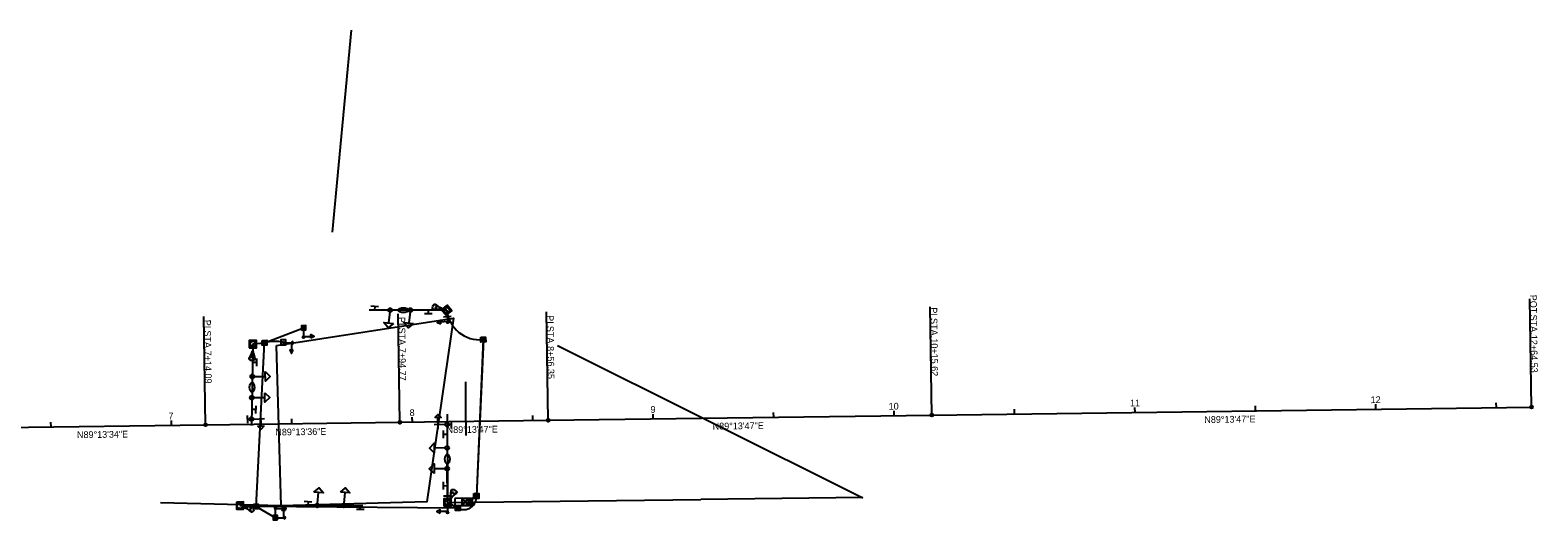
# Model space of a CAD drawing. Extents: x 1369241 to 1370511, y 405823 to 406278.
# Drawn here: x 1369885 to 1370511, y 405870 to 406073 of the extents above; entities that cross this region are included whole.
import ezdxf

# ---------------------------------------------------------------- set-up
doc = ezdxf.new("R2010")
doc.units = 0
for name, color, linetype in [('_CIVIL_CONSTRUCTION', 7, 'Continuous'), ('CM_Corridor_Conceptual', 7, 'Continuous'), ('CM_Corridor_Range_Conceptual', 7, 'Continuous'), ('DT_P_Tie', 7, 'Continuous'), ('GE_P_Alignment', 7, 'Continuous'), ('MD_P_ACB_B', 7, 'Continuous'), ('MD_P_ACIC_B', 7, 'Continuous'), ('MD_P_ACSC_T', 7, 'Continuous'), ('MD_P_CSS_B', 7, 'Continuous'), ('MD_P_CURB_FACE_BOT', 7, 'Continuous'), ('MD_P_CURB_FACE_TOP', 7, 'Continuous'), ('PF_X_Ground_Line', 7, 'Continuous'), ('PM_P_Crosswalk', 7, 'Continuous'), ('PV_P_Curb', 7, 'Continuous'), ('SC_Scratch1', 7, 'Continuous')]:
    doc.layers.add(name, color=color, linetype=linetype)

msp = doc.modelspace()

# ---------------------------------------------------------------- linework, layer by layer
at = {"layer": '_CIVIL_CONSTRUCTION'}
for p, q in [((1370064.71, 405879.01), (1370067.4, 405876.02)), ((1370067.38, 405879.02), (1370064.73, 405876.01)), ((1370067.38, 405878.33), (1370068.64, 405876.72)), ((1370068.63, 405878.34), (1370067.39, 405876.71))]:
    msp.add_line(p, q, dxfattribs=at)
for points in [[(1370061.71, 405878.99), (1370061.73, 405875.99), (1370069.11, 405876.03), (1370069.09, 405879.03)], [(1370061.71, 405878.99), (1370061.73, 405875.99), (1370064.73, 405876.01), (1370064.71, 405879.01)], [(1370064.71, 405879.01), (1370067.38, 405879.02), (1370067.4, 405876.02), (1370064.73, 405876.01)], [(1370067.38, 405878.33), (1370068.63, 405878.34), (1370068.64, 405876.72), (1370067.39, 405876.71)]]:
    msp.add_lwpolyline(points, close=True, dxfattribs=at)
at = {"layer": 'CM_Corridor_Conceptual'}
for p, q in [((1370034.8, 405956.39), (1370034.25, 405951.83)), ((1370043.15, 405956.39), (1370042.6, 405951.83)), ((1370058.37, 405957.17), (1370058.37, 405957.17)), ((1369998.96, 405950.98), (1369998.96, 405950.98)), ((1369989.24, 405943.6), (1369989.24, 405943.6)), ((1369978.46, 405929.56), (1369983.06, 405929.61)), ((1369978.3, 405920.83), (1369982.9, 405920.88)), ((1369978.13, 405911.95), (1369982.73, 405912.14)), ((1369981.04, 405913.79), (1369981.24, 405909.09)), ((1370057.75, 405909.6), (1370053.15, 405909.53)), ((1370054.79, 405907.83), (1370054.72, 405912.53)), ((1370057.74, 405899.92), (1370053.14, 405899.87)), ((1370057.74, 405891.31), (1370053.14, 405891.26)), ((1370004.7, 405876.85), (1370005.16, 405881.42)), ((1370015.75, 405876.85), (1370016.21, 405881.42)), ((1370058.66, 405878.19), (1370058.66, 405878.19)), ((1369986.06, 405870.97), (1369986.06, 405870.97)), ((1369987.25, 405870.08), (1369987.25, 405870.08))]:
    msp.add_line(p, q, dxfattribs=at)
for points in [[(1370036.23, 405951.59), (1370034.01, 405949.84), (1370032.26, 405952.07)], [(1370044.59, 405951.59), (1370042.36, 405949.84), (1370040.62, 405952.07)], [(1370055.9, 405951.5), (1370055.76, 405952.9), (1370054.44, 405952.07)], [(1370001.96, 405945.58), (1370001.96, 405946.98), (1370003.36, 405946.28)], [(1369994.64, 405940.6), (1369993.24, 405940.6), (1369993.94, 405939.2)], [(1369983.04, 405931.61), (1369985.06, 405929.63), (1369983.08, 405927.61)], [(1369982.87, 405922.88), (1369984.9, 405920.9), (1369982.92, 405918.88)], [(1369982.56, 405909.15), (1369981.29, 405907.76), (1369979.9, 405909.04)], [(1370053.39, 405912.51), (1370054.7, 405913.86), (1370056.06, 405912.55)], [(1370053.17, 405897.87), (1370051.15, 405899.85), (1370053.12, 405901.87)], [(1370053.17, 405889.27), (1370051.14, 405891.25), (1370053.12, 405893.27)], [(1370003.17, 405881.62), (1370005.36, 405883.41), (1370007.15, 405881.22)], [(1370014.22, 405881.62), (1370016.41, 405883.41), (1370018.2, 405881.22)], [(1369991.46, 405873.97), (1369990.06, 405873.97), (1369990.76, 405875.37)], [(1369990.26, 405875.47), (1369990.26, 405874.07), (1369991.66, 405874.77)], [(1370055.66, 405872.79), (1370055.66, 405874.19), (1370054.26, 405873.49)]]:
    msp.add_lwpolyline(points, close=True, dxfattribs=at)
for points in [[(1370058.48, 405955.97), (1370058.82, 405952.49), (1370055.83, 405952.2)], [(1369998.96, 405949.78), (1369998.96, 405946.28), (1370001.96, 405946.28)], [(1369990.44, 405943.6), (1369993.94, 405943.6), (1369993.94, 405940.6)], [(1370058.66, 405876.99), (1370058.66, 405873.49), (1370055.66, 405873.49)], [(1369987.26, 405871.28), (1369987.26, 405874.78), (1369990.26, 405874.77)], [(1369987.26, 405870.97), (1369990.76, 405870.97), (1369990.76, 405873.97)]]:
    msp.add_lwpolyline(points, dxfattribs=at)
for centre in [(1370034.89, 405957.19), (1370043.25, 405957.19), (1369977.66, 405929.55), (1369977.5, 405920.82), (1369977.33, 405911.92), (1370058.55, 405909.61), (1370058.54, 405899.93), (1370058.54, 405891.32), (1370004.62, 405876.05), (1370015.67, 405876.05)]:
    msp.add_circle(centre, 0.8, dxfattribs=at)
at = {"layer": 'CM_Corridor_Range_Conceptual'}
for p, q in [((1370026.9, 405958.92), (1370030.08, 405958.65)), ((1370028.49, 405958.78), (1370028.35, 405957.19)), ((1370028.49, 405958.78), (1370028.49, 405958.78)), ((1370052.37, 405955.58), (1370049.17, 405955.6)), ((1370050.77, 405955.59), (1370050.78, 405957.19)), ((1370050.77, 405955.59), (1370050.77, 405955.59)), ((1370060.22, 405954.52), (1370057.03, 405954.23)), ((1370058.63, 405954.38), (1370058.48, 405955.97)), ((1370058.63, 405954.38), (1370058.63, 405954.38)), ((1369979.37, 405935.46), (1369977.77, 405935.43)), ((1369979.34, 405937.06), (1369979.4, 405933.86)), ((1369979.37, 405935.46), (1369979.37, 405935.46)), ((1369979.02, 405915.89), (1369977.42, 405915.96)), ((1369979.09, 405917.48), (1369978.95, 405914.29)), ((1369979.02, 405915.89), (1369979.02, 405915.89)), ((1369975.76, 405910.27), (1369975.71, 405913.47)), ((1369975.73, 405911.87), (1369977.33, 405911.9)), ((1369975.74, 405911.87), (1369975.74, 405911.87)), ((1370060.15, 405909.6), (1370058.55, 405909.59)), ((1370060.15, 405911.2), (1370060.15, 405908)), ((1370060.15, 405909.6), (1370060.15, 405909.6)), ((1370056.98, 405903.99), (1370056.97, 405907.19)), ((1370056.97, 405905.59), (1370058.57, 405905.59)), ((1370056.97, 405905.59), (1370056.97, 405905.59)), ((1370056.99, 405882.68), (1370057.08, 405885.88)), ((1370057.03, 405884.28), (1370058.63, 405884.23)), ((1370057.03, 405884.28), (1370057.03, 405884.28)), ((1369999.19, 405877.8), (1370002.38, 405877.53)), ((1370000.79, 405877.66), (1370000.65, 405876.07)), ((1370000.79, 405877.66), (1370000.79, 405877.66)), ((1370057.06, 405880.08), (1370060.26, 405880.07)), ((1370058.66, 405880.08), (1370058.66, 405878.48)), ((1370058.66, 405880.08), (1370058.66, 405880.08)), ((1370024.05, 405874.41), (1370020.85, 405874.43)), ((1370022.45, 405874.42), (1370022.45, 405876.02)), ((1370022.45, 405874.42), (1370022.45, 405874.42))]:
    msp.add_line(p, q, dxfattribs=at)
at = {"layer": 'DT_P_Tie'}
for p, q in [((1370055.54, 405958.22), (1370053.77, 405959.56)), ((1370055.54, 405958.22), (1370053.77, 405959.56)), ((1370055.34, 405957.5), (1370055.54, 405958.22)), ((1370055.34, 405957.5), (1370053.14, 405957.24)), ((1370053.14, 405957.24), (1370055.34, 405957.5)), ((1370057.19, 405957.38), (1370056.16, 405957.66)), ((1370059.38, 405952.44), (1370058.27, 405952.34)), ((1370058.48, 405955.97), (1370058.83, 405952.39)), ((1369998.4, 405946.18), (1369999.52, 405946.18)), ((1369998.96, 405949.78), (1369998.96, 405946.18)), ((1369977.35, 405939.24), (1369976.34, 405937.27)), ((1369977.35, 405939.24), (1369976.34, 405937.27)), ((1369978.1, 405939.17), (1369977.35, 405939.24)), ((1369977.89, 405941.01), (1369977.79, 405939.95)), ((1369978.1, 405939.17), (1369978.73, 405937.05)), ((1369978.73, 405937.05), (1369978.1, 405939.17)), ((1369990.44, 405943.6), (1369994.04, 405943.6)), ((1369994.04, 405944.16), (1369994.04, 405943.04)), ((1370058.66, 405876.99), (1370058.66, 405873.39)), ((1370059.34, 405878.28), (1370059.87, 405879.2)), ((1370059.92, 405880.04), (1370060.23, 405882.23)), ((1370060.23, 405882.23), (1370059.92, 405880.04)), ((1370059.92, 405880.04), (1370060.57, 405879.66)), ((1370060.57, 405879.66), (1370062.31, 405881.03)), ((1370060.57, 405879.66), (1370062.31, 405881.03)), ((1369973.71, 405875.66), (1369974.73, 405875.36)), ((1369975.55, 405875.5), (1369975.34, 405874.78)), ((1369975.34, 405874.78), (1369977.07, 405873.4)), ((1369975.34, 405874.78), (1369977.07, 405873.4)), ((1369975.55, 405875.5), (1369977.76, 405875.7)), ((1369977.76, 405875.7), (1369975.55, 405875.5)), ((1369986.69, 405874.77), (1369987.81, 405874.77)), ((1369987.25, 405871.17), (1369987.25, 405874.77)), ((1369987.26, 405870.97), (1369990.86, 405870.97)), ((1369990.86, 405871.53), (1369990.86, 405870.41)), ((1370059.22, 405873.39), (1370058.1, 405873.39))]:
    msp.add_line(p, q, dxfattribs=at)
for points in [[(1370056.07, 405957.3), (1370056.26, 405958.02), (1370055.54, 405958.22), (1370055.34, 405957.5)], [(1369978.17, 405939.92), (1369977.42, 405939.99), (1369977.35, 405939.24), (1369978.1, 405939.17)], [(1370059.54, 405879.39), (1370060.19, 405879.01), (1370060.57, 405879.66), (1370059.92, 405880.04)], [(1369974.83, 405875.72), (1369974.62, 405875), (1369975.34, 405874.78), (1369975.55, 405875.5)]]:
    msp.add_lwpolyline(points, close=True, dxfattribs=at)
for points in [[(1370056.07, 405957.3), (1370056.26, 405958.02), (1370055.54, 405958.22), (1370055.34, 405957.5), (1370056.07, 405957.3)], [(1369978.17, 405939.92), (1369977.42, 405939.99), (1369977.35, 405939.24), (1369978.1, 405939.17), (1369978.17, 405939.92)], [(1370059.54, 405879.39), (1370060.19, 405879.01), (1370060.57, 405879.66), (1370059.92, 405880.04), (1370059.54, 405879.39)], [(1369974.83, 405875.72), (1369974.62, 405875), (1369975.34, 405874.78), (1369975.55, 405875.5), (1369974.83, 405875.72)]]:
    msp.add_lwpolyline(points, dxfattribs=at)
for centre, start, end in [((1370058.83, 405952.39), 185.47946, 5.47907), ((1369998.96, 405946.18), 180.00019, 359.99981), ((1369994.04, 405943.6), 270.00019, 89.99981), ((1369987.25, 405874.77), 0.00019, 179.99981), ((1369990.86, 405870.97), 270.00019, 89.99981), ((1370058.66, 405873.39), 180.00019, 359.99981)]:
    msp.add_arc(centre, 0.56, start, end, dxfattribs=at)
for centre, major_axis in [((1370053.28, 405958.45), (0.33, 1.2)), ((1369977.52, 405936.97), (-1.23, 0.11)), ((1370061.36, 405881.8), (1.07, -0.62)), ((1369977.6, 405874.5), (-0.35, -1.19))]:
    msp.add_ellipse(centre, major_axis=major_axis, ratio=0.621318, dxfattribs=at)
for centre, major_axis in [((1370053.28, 405958.45), (0.33, 1.2)), ((1369977.52, 405936.97), (-1.23, 0.11)), ((1370061.36, 405881.8), (1.07, -0.62)), ((1369977.6, 405874.5), (-0.35, -1.19))]:
    msp.add_ellipse(centre, major_axis=major_axis, ratio=0.621318, start_param=3.386213, end_param=6.038231, dxfattribs=at)
at = {"layer": 'GE_P_Alignment'}
for points in [[(1370058.13, 405955.06), (1370060.48, 405956.93), (1370058.61, 405959.27), (1370056.26, 405957.41)], [(1369998.09, 405948.9), (1369999.89, 405948.92), (1369999.87, 405950.72), (1369998.07, 405950.7)], [(1369976.36, 405941.54), (1369979.36, 405941.54), (1369979.36, 405944.54), (1369976.36, 405944.54)], [(1369989.53, 405942.78), (1369991.53, 405942.79), (1369991.53, 405944.79), (1369989.53, 405944.78)], [(1369971.04, 405877.47), (1369971.06, 405874.47), (1369974.06, 405874.49), (1369974.04, 405877.49)], [(1370057.18, 405875.78), (1370060.18, 405875.8), (1370060.15, 405878.8), (1370057.15, 405878.78)], [(1369988.15, 405870.06), (1369988.16, 405871.86), (1369986.36, 405871.87), (1369986.35, 405870.07)]]:
    msp.add_lwpolyline(points, close=True, dxfattribs=at)
for centre, radius in [((1370058.37, 405957.17), 1.2), ((1369998.98, 405949.81), 0.3), ((1369977.86, 405943.04), 1.2), ((1369972.55, 405875.98), 1.2), ((1370058.66, 405877.29), 1.2), ((1369987.26, 405870.97), 0.3)]:
    msp.add_circle(centre, radius, dxfattribs=at)
msp.add_ellipse((1369990.53, 405943.78), major_axis=(-0.001, 0.333), ratio=0.99991, dxfattribs=at)
at = {"layer": 'MD_P_ACB_B'}
for p, q in [((1369982.71, 405943.63), (1369982.71, 405943.63)), ((1370073.52, 405944.92), (1370073.52, 405944.92)), ((1370070.66, 405879.99), (1370070.66, 405879.99)), ((1369979.14, 405875.63), (1369979.14, 405875.63)), ((1370062.97, 405874.89), (1370062.97, 405874.89))]:
    msp.add_line(p, q, dxfattribs=at)
for points in [[(1370072.51, 405945.91), (1370074.51, 405945.93), (1370074.53, 405943.93), (1370072.53, 405943.91)], [(1369981.69, 405944.61), (1369983.69, 405944.64), (1369983.72, 405942.64), (1369981.72, 405942.61)], [(1369978.12, 405876.61), (1369980.12, 405876.64), (1369980.15, 405874.64), (1369978.15, 405874.61)], [(1370069.65, 405880.98), (1370071.65, 405880.99), (1370071.66, 405879), (1370069.67, 405878.98)], [(1370061.97, 405875.89), (1370063.97, 405875.9), (1370063.98, 405873.9), (1370061.98, 405873.89)]]:
    msp.add_lwpolyline(points, close=True, dxfattribs=at)
for points in [[(1370072.61, 405945.57), (1370073.44, 405945.58)], [(1370073.03, 405945.58), (1370073.05, 405944.25)], [(1370073.6, 405944.25), (1370073.59, 405945.59), (1370074.09, 405945.59), (1370074.14, 405945.58), (1370074.22, 405945.56), (1370074.25, 405945.54), (1370074.28, 405945.52), (1370074.32, 405945.47), (1370074.36, 405945.42), (1370074.38, 405945.33), (1370074.38, 405945.21), (1370074.37, 405945.17), (1370074.35, 405945.1), (1370074.31, 405945.03), (1370074.27, 405945), (1370074.23, 405944.97), (1370074.21, 405944.96), (1370074.18, 405944.95), (1370074.09, 405944.94), (1370073.6, 405944.94)], [(1369981.8, 405944.28), (1369982.62, 405944.29)], [(1369982.22, 405944.29), (1369982.23, 405942.95)], [(1369982.79, 405942.96), (1369982.77, 405944.29), (1369983.28, 405944.3), (1369983.33, 405944.29), (1369983.4, 405944.27), (1369983.44, 405944.25), (1369983.47, 405944.23), (1369983.51, 405944.18), (1369983.54, 405944.13), (1369983.56, 405944.04), (1369983.57, 405943.92), (1369983.56, 405943.87), (1369983.54, 405943.81), (1369983.49, 405943.74), (1369983.45, 405943.71), (1369983.42, 405943.68), (1369983.4, 405943.67), (1369983.37, 405943.66), (1369983.28, 405943.65), (1369982.78, 405943.64)], [(1369983.28, 405943.65), (1369983.58, 405942.97)], [(1370074.09, 405944.94), (1370074.39, 405944.26)], [(1370069.75, 405880.65), (1370070.58, 405880.66)], [(1370070.17, 405880.65), (1370070.18, 405879.32)], [(1370070.74, 405879.32), (1370070.73, 405880.66), (1370071.23, 405880.66), (1370071.29, 405880.65), (1370071.36, 405880.63), (1370071.39, 405880.61), (1370071.42, 405880.59), (1370071.47, 405880.53), (1370071.5, 405880.48), (1370071.52, 405880.4), (1370071.52, 405880.27), (1370071.51, 405880.23), (1370071.49, 405880.17), (1370071.45, 405880.09), (1370071.4, 405880.06), (1370071.37, 405880.04), (1370071.35, 405880.03), (1370071.32, 405880.02), (1370071.23, 405880.01), (1370070.73, 405880.01)], [(1370071.23, 405880.01), (1370071.52, 405879.33)], [(1369978.22, 405876.28), (1369979.05, 405876.29)], [(1369978.64, 405876.29), (1369978.66, 405874.95)], [(1369979.22, 405874.96), (1369979.2, 405876.29), (1369979.7, 405876.3), (1369979.76, 405876.29), (1369979.83, 405876.27), (1369979.86, 405876.25), (1369979.89, 405876.23), (1369979.94, 405876.18), (1369979.97, 405876.13), (1369979.99, 405876.04), (1369979.99, 405875.92), (1369979.98, 405875.88), (1369979.96, 405875.81), (1369979.92, 405875.74), (1369979.88, 405875.71), (1369979.85, 405875.68), (1369979.83, 405875.67), (1369979.8, 405875.66), (1369979.7, 405875.65), (1369979.21, 405875.64)], [(1369979.7, 405875.65), (1369980.01, 405874.97)], [(1370062.06, 405875.56), (1370062.89, 405875.56)], [(1370062.48, 405875.56), (1370062.49, 405874.22)], [(1370063.05, 405874.23), (1370063.04, 405875.56), (1370063.55, 405875.56), (1370063.6, 405875.55), (1370063.67, 405875.53), (1370063.7, 405875.51), (1370063.74, 405875.49), (1370063.78, 405875.44), (1370063.81, 405875.39), (1370063.83, 405875.3), (1370063.83, 405875.18), (1370063.82, 405875.14), (1370063.8, 405875.07), (1370063.76, 405875), (1370063.72, 405874.97), (1370063.69, 405874.95), (1370063.67, 405874.93), (1370063.63, 405874.92), (1370063.54, 405874.91), (1370063.05, 405874.91)], [(1370063.54, 405874.91), (1370063.84, 405874.23)]]:
    msp.add_lwpolyline(points, dxfattribs=at)
at = {"layer": 'MD_P_ACIC_B'}
for p, q in [((1369982.71, 405943.63), (1369998.96, 405949.78)), ((1369977.88, 405943.12), (1369982.71, 405943.63)), ((1369979.21, 405875.62), (1369982.71, 405943.63)), ((1370073.52, 405944.92), (1370070.66, 405879.99)), ((1370058.66, 405877.29), (1370062.97, 405874.89)), ((1370062.97, 405874.89), (1370058.72, 405877.29)), ((1370063.05, 405874.85), (1370066.06, 405877.51)), ((1369972.55, 405875.98), (1369979.14, 405875.63)), ((1370062.97, 405874.89), (1369979.21, 405875.62)), ((1369979.21, 405875.62), (1369987.26, 405870.97))]:
    msp.add_line(p, q, dxfattribs=at)
for centre, radius, start, end in [((1370072.11, 405958.67), 13.82, 186.24833, 275.85177), ((1369986.98, 405928.56), 15.63, 76.8666, 105.21268), ((1370065.45, 405879.54), 5.23, 242.65814, 4.93942)]:
    msp.add_arc(centre, radius, start, end, dxfattribs=at)
at = {"layer": 'MD_P_ACSC_T'}
for p, q in [((1370058.37, 405957.17), (1370042.37, 405957.17)), ((1369977.93, 405943.12), (1369977.59, 405927.12)), ((1370058.72, 405877.3), (1370058.6, 405893.3))]:
    msp.add_line(p, q, dxfattribs=at)
for centre in [(1370058.37, 405957.17), (1369977.93, 405943.12), (1370058.72, 405877.3)]:
    msp.add_circle(centre, 1.1, dxfattribs=at)
for centre, major_axis in [((1370040.37, 405957.17), (-2, 0)), ((1369977.55, 405925.12), (-0.04, -2)), ((1370058.6, 405895.3), (-0.01, 2))]:
    msp.add_ellipse(centre, major_axis=major_axis, ratio=0.5, dxfattribs=at)
at = {"layer": 'MD_P_CSS_B'}
for p, q in [((1370144.09, 405912.02), (1370144.06, 405914.02)), ((1370194.08, 405912.69), (1370194.05, 405914.69)), ((1370244.08, 405913.36), (1370244.05, 405915.36)), ((1370259.7, 405913.57), (1370508.58, 405916.92)), ((1370294.07, 405914.03), (1370294.05, 405916.03)), ((1370344.07, 405914.7), (1370344.04, 405916.7)), ((1370394.06, 405915.38), (1370394.04, 405917.38)), ((1370444.06, 405916.05), (1370444.03, 405918.05)), ((1370494.05, 405916.72), (1370494.03, 405918.72)), ((1369874.22, 405908.38), (1369958.19, 405909.51)), ((1369894.11, 405908.65), (1369894.08, 405910.65)), ((1369944.1, 405909.32), (1369944.08, 405911.32)), ((1369958.19, 405909.51), (1370038.86, 405910.6)), ((1369994.1, 405910), (1369994.07, 405912)), ((1370038.86, 405910.6), (1370100.44, 405911.43)), ((1370044.09, 405910.67), (1370044.07, 405912.67)), ((1370094.09, 405911.34), (1370094.06, 405913.34)), ((1370100.44, 405911.43), (1370259.7, 405913.57))]:
    msp.add_line(p, q, dxfattribs=at)
at = {"layer": 'MD_P_CURB_FACE_BOT'}
msp.add_line((1370104.3, 405942.47), (1370231.02, 405879.25), dxfattribs=at)
at = {"layer": 'MD_P_CURB_FACE_TOP'}
msp.add_line((1370058.66, 405877.29), (1370163.85, 405878.52), dxfattribs=at)
at = {"layer": 'PF_X_Ground_Line'}
msp.add_lwpolyline([(1369987.68, 405942.54), (1370061.12, 405953.86), (1370050.05, 405877.5), (1369989.67, 405875.86)], close=True, dxfattribs=at)
at = {"layer": 'PM_P_Crosswalk'}
for p, q in [((1370259.7, 405913.57), (1370259.09, 405958.57)), ((1370508.58, 405916.92), (1370507.97, 405961.91)), ((1369958.19, 405909.51), (1369957.59, 405954.51)), ((1370038.86, 405910.6), (1370038.26, 405955.6)), ((1370100.44, 405911.43), (1370099.84, 405956.43)), ((1370073.6, 405944.92), (1370070.66, 405879.99)), ((1370066.09, 405927.4), (1370066.2, 405916.85)), ((1370066.2, 405916.85), (1370066.31, 405905.12)), ((1369989.67, 405875.86), (1369939.59, 405877.13)), ((1370231.04, 405879.34), (1370163.86, 405878.56))]:
    msp.add_line(p, q, dxfattribs=at)
for centre in [(1370259.7, 405913.57), (1370508.58, 405916.92), (1369958.19, 405909.51), (1370038.86, 405910.6), (1370100.44, 405911.43)]:
    msp.add_circle(centre, 0.6, dxfattribs=at)
at = {"layer": 'PV_P_Curb'}
msp.add_line((1370010.95, 405989.49), (1370018.81, 406073.44), dxfattribs=at)
at = {"layer": 'SC_Scratch1'}
for p, q in [((1370058.37, 405957.17), (1370026.14, 405957.19)), ((1369977.88, 405943.12), (1369977.28, 405909.21)), ((1370058.54, 405913.96), (1370058.65, 405878.61)), ((1369972.67, 405876.08), (1370023.5, 405876.02))]:
    msp.add_line(p, q, dxfattribs=at)

# ---------------------------------------------------------------- texts
at = {"layer": 'DT_P_Tie'}
for rotation, p in [(164.77075, (1370053.99, 405958.98)), (264.80328, (1369976.87, 405937.58)), (60.07361, (1370061.7, 405880.97)), (343.39794, (1369976.87, 405873.98))]:
    msp.add_text('S', height=1.4, rotation=rotation, dxfattribs=at).set_placement(p)
at = {"layer": 'MD_P_CSS_B'}
for s, rotation, p in [('12', 0.77029, (1370441.86, 405918.52)), ('7', 0.77388, (1369942.89, 405911.81)), ('8', 0.77029, (1370042.96, 405913.16)), ('9', 0.77029, (1370142.97, 405914.5)), ('10', 0.77029, (1370241.81, 405915.83)), ('11', 0.77029, (1370342, 405917.18))]:
    msp.add_text(s, height=2.8, rotation=rotation, dxfattribs=at).set_placement(p)
at = {"layer": 'PM_P_Crosswalk'}
for s, rotation, p in [('PI', 270.77029, (1370259.14, 405958.28)), ('POT', 270.77029, (1370507.99, 405963.52)), ('PI', 270.7732, (1369957.65, 405953.14)), ('PI', 270.77029, (1370038.32, 405954.33)), ('PI', 270.77029, (1370099.9, 405955.04)), (' STA. ', 270.77029, (1370259.19, 405954.89)), (' STA. ', 270.77029, (1370508.09, 405956.32)), (' STA. ', 270.7732, (1369957.69, 405949.75)), (' STA. ', 270.77029, (1370038.36, 405950.94)), (' STA. ', 270.77029, (1370099.94, 405951.65)), ('12+64.53', 270.77029, (1370508.22, 405946.87)), ('7+14.09', 270.7732, (1369957.82, 405940.3)), ('7+94.77', 270.77029, (1370038.49, 405941.49)), ('8+56.35', 270.77029, (1370100.07, 405942.2)), ('10+15.62', 270.77029, (1370259.31, 405945.43)), ('N89°13\'36"E', 0.7732, (1369987.23, 405905.1)), ('N89°13\'47"E', 0.77029, (1370058.35, 405906.06)), ('N89°13\'47"E', 0.77029, (1370168.77, 405907.55)), ('N89°13\'47"E', 0.77029, (1370372.84, 405910.29)), ('N89°13\'34"E', 0.77388, (1369904.91, 405903.99))]:
    msp.add_text(s, height=2.8, rotation=rotation, dxfattribs=at).set_placement(p)

doc.saveas('drawing.dxf')
